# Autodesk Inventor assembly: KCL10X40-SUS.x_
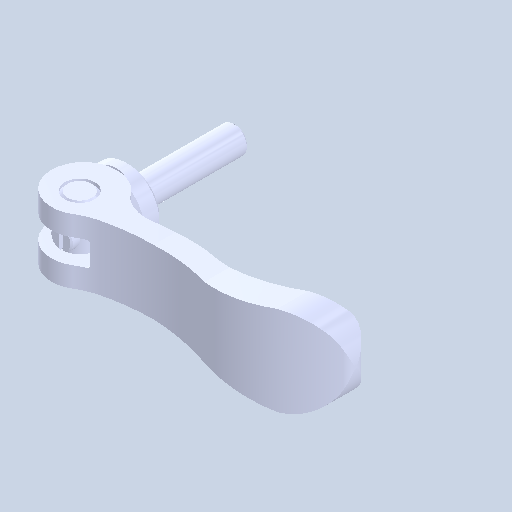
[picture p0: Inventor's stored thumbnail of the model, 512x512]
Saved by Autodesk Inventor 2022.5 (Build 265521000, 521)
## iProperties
Created: 2024-08
Part Number: KCL10X40-SUS.x_
Document SubType Name: Assembly
Designer: ImaoCorp
Author: ImaoCorp
Sending System: SOLIDWORKS 2022-2022290
MC: AMD64
MC_MODEL: Intel64 Family 6 Model 60 Stepping 3, GenuineIntel
OS: Windows_NT
FRU: Parasolid Version 33.1, build 260,  4-25-2022
FORMAT: text
GUISE: transmit
KEY: FILEKCL10X40-SUS.x_t
DATE: Thu Aug 29 10:51:09 2024
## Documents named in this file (5)
- Y:\5.更新分\2024年対応\1001_KCL\データ\kcl10x40-sus\KCL10X40-SUS.x_.iam
- Y:\5.更新分\2024年対応\1001_KCL\データ\kcl10x40-sus\KCL10X40-SUS_01.ipt
- Y:\5.更新分\2024年対応\1001_KCL\データ\kcl10x40-sus\KCL10X40-SUS_02.ipt
- Y:\5.更新分\2024年対応\1001_KCL\データ\kcl10x40-sus\KCL10X40-SUS_03.ipt
- Y:\5.更新分\2024年対応\1001_KCL\データ\kcl10x40-sus\KCL10X40-SUS_04.ipt
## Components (4 placed, 4 different names)
1. KCL10X40-SUS_01
2. KCL10X40-SUS_02
3. KCL10X40-SUS_03
4. KCL10X40-SUS_04
